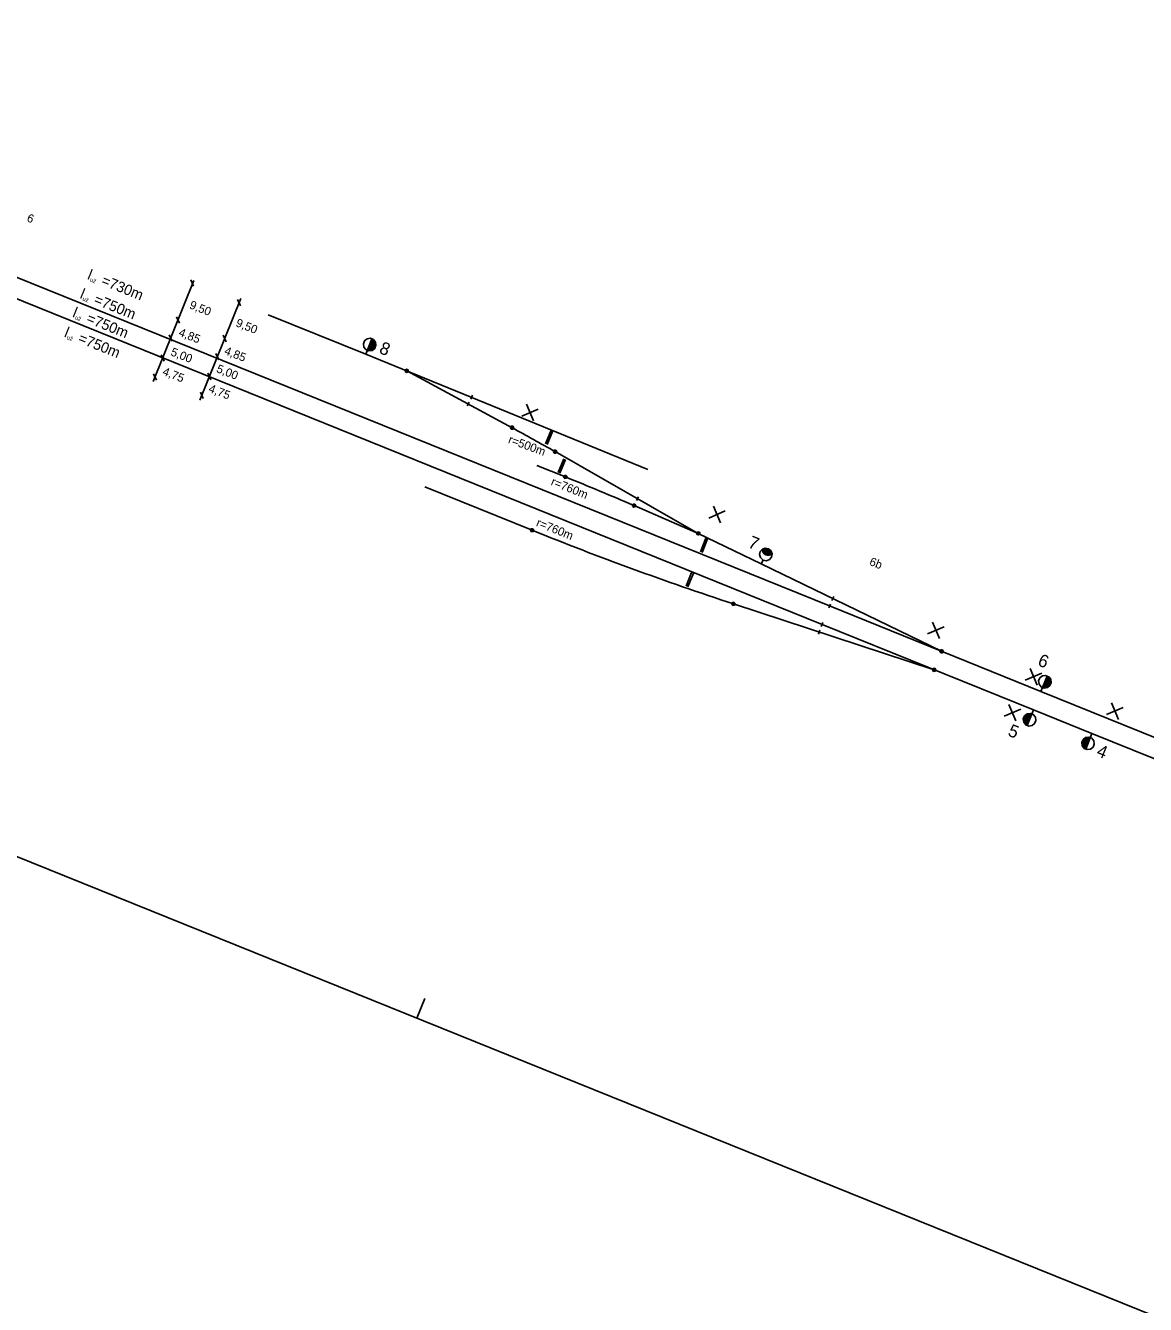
# Model space of a CAD drawing. Extents: x -467542 to -465211, y -1328177 to -1327037.
# Drawn here: x -466272 to -466005.7, y -1327930.8 to -1327626.7 of the extents above; entities that cross this region are included whole.
import ezdxf

# ---------------------------------------------------------------- set-up
doc = ezdxf.new("R2010")
doc.units = 0
for name, color, linetype in [('Level 1', 7, 'Continuous'), ('Level 10', 7, 'Continuous'), ('Level 11', 7, 'Continuous'), ('Level 61', 7, 'Continuous')]:
    doc.layers.add(name, color=color, linetype=linetype)

msp = doc.modelspace()

# ---------------------------------------------------------------- linework, layer by layer
at = {"layer": 'Level 1'}
for p, q in [((-466274.42, -1327686.43), (-466080.84, -1327764.72)), ((-466276.18, -1327690.84), (-466082.62, -1327769.13)), ((-466214.3, -1327695.52), (-466191.13, -1327704.89)), ((-466191.13, -1327704.89), (-466124.03, -1327732.27)), ((-466181.37, -1327708.84), (-466181.37, -1327708.84)), ((-466181.37, -1327708.84), (-466156.34, -1327722.35)), ((-466166.16, -1327715.53), (-466165.78, -1327714.6)), ((-466165.97, -1327715.07), (-466165.97, -1327715.07)), ((-466166.99, -1327717.17), (-466166.51, -1327716.29)), ((-466166.75, -1327716.73), (-466166.75, -1327716.73)), ((-466156.34, -1327722.35), (-466156.34, -1327722.35)), ((-466112.05, -1327747.46), (-466146.12, -1327728.03)), ((-466146.12, -1327728.03), (-466146.12, -1327728.03)), ((-466150.41, -1327731.3), (-466143.65, -1327734.04)), ((-466177.06, -1327736.41), (-466151.55, -1327746.72)), ((-466143.65, -1327734.04), (-466143.65, -1327734.04)), ((-466126.73, -1327739.66), (-466126.24, -1327738.79)), ((-466126.73, -1327739.66), (-466126.24, -1327738.79)), ((-466126.49, -1327739.22), (-466126.49, -1327739.22)), ((-466126.49, -1327739.22), (-466126.49, -1327739.22)), ((-466127.51, -1327741.33), (-466127.11, -1327740.41)), ((-466127.31, -1327740.87), (-466127.31, -1327740.87)), ((-466127.31, -1327740.87), (-466112.05, -1327747.46)), ((-466127.31, -1327740.87), (-466127.31, -1327740.87)), ((-466151.55, -1327746.72), (-466151.55, -1327746.72)), ((-466097.1, -1327754.7), (-466112.06, -1327747.46)), ((-466112.05, -1327747.46), (-466112.05, -1327747.46)), ((-466054.2, -1327775.5), (-466097.1, -1327754.7)), ((-466055.98, -1327779.9), (-466103.7, -1327764.23)), ((-466103.7, -1327764.23), (-466103.7, -1327764.23)), ((-466080.66, -1327764.26), (-466081.03, -1327765.19)), ((-466079.84, -1327762.51), (-466080.28, -1327763.41)), ((-466080.06, -1327762.96), (-466080.06, -1327762.96)), ((-466030.58, -1327785.05), (-466080.84, -1327764.72)), ((-466080.84, -1327764.72), (-466080.84, -1327764.72)), ((-466082.81, -1327769.59), (-466082.44, -1327768.66)), ((-466032.36, -1327789.45), (-466082.62, -1327769.13)), ((-466082.62, -1327769.13), (-466082.62, -1327769.13)), ((-466083.44, -1327771.41), (-466083.13, -1327770.46)), ((-466083.29, -1327770.94), (-466083.29, -1327770.94)), ((-466054.2, -1327775.5), (-466054.2, -1327775.5)), ((-466055.98, -1327779.9), (-466055.98, -1327779.9)), ((-466030.58, -1327785.05), (-465963.83, -1327812.05)), ((-466032.36, -1327789.45), (-466018.46, -1327795.08)), ((-466018.46, -1327795.08), (-465979.9, -1327810.67))]:
    msp.add_line(p, q, dxfattribs=at)
for points in [[(-466181, -1327708.99), (-466181.06, -1327708.59), (-466181.43, -1327708.44), (-466181.74, -1327708.69), (-466181.69, -1327709.08), (-466181.32, -1327709.23), (-466181, -1327708.99)], [(-466156.53, -1327722.7), (-466156.74, -1327722.36), (-466156.55, -1327722.01), (-466156.15, -1327722), (-466155.94, -1327722.34), (-466156.13, -1327722.69), (-466156.53, -1327722.7)], [(-466145.92, -1327727.68), (-466145.72, -1327728.02), (-466145.92, -1327728.37), (-466146.32, -1327728.37), (-466146.52, -1327728.03), (-466146.32, -1327727.68), (-466145.92, -1327727.68)], [(-466143.49, -1327733.67), (-466143.25, -1327733.98), (-466143.4, -1327734.35), (-466143.79, -1327734.41), (-466144.04, -1327734.09), (-466143.89, -1327733.72), (-466143.49, -1327733.67)], [(-466127.47, -1327741.24), (-466127.7, -1327740.92), (-466127.54, -1327740.55), (-466127.15, -1327740.5), (-466126.91, -1327740.82), (-466127.07, -1327741.19), (-466127.47, -1327741.24)], [(-466151.4, -1327746.35), (-466151.16, -1327746.67), (-466151.31, -1327747.03), (-466151.7, -1327747.09), (-466151.95, -1327746.78), (-466151.8, -1327746.41), (-466151.4, -1327746.35)], [(-466112.42, -1327747.3), (-466112.1, -1327747.06), (-466111.73, -1327747.22), (-466111.69, -1327747.61), (-466112.01, -1327747.85), (-466112.37, -1327747.7), (-466112.42, -1327747.3)], [(-466103.82, -1327764.61), (-466104.09, -1327764.32), (-466103.96, -1327763.94), (-466103.57, -1327763.85), (-466103.3, -1327764.15), (-466103.43, -1327764.53), (-466103.82, -1327764.61)], [(-466054.37, -1327775.86), (-466053.97, -1327775.83), (-466053.8, -1327775.47), (-466054.02, -1327775.14), (-466054.42, -1327775.17), (-466054.6, -1327775.53), (-466054.37, -1327775.86)], [(-466055.85, -1327779.52), (-466055.59, -1327779.82), (-466055.71, -1327780.2), (-466056.1, -1327780.28), (-466056.37, -1327779.98), (-466056.24, -1327779.6), (-466055.85, -1327779.52)]]:
    msp.add_lwpolyline(points, dxfattribs=at)
for centre, radius, start, end in [((-466393.87, -1328162.33), 500, 60.2972, 61.637), ((-466428.6, -1328438.6), 760, 66.64451, 67.97957), ((-465866.6, -1327042.17), 760, 247.97922, 251.82173)]:
    msp.add_arc(centre, radius, start, end, dxfattribs=at)
at = {"layer": 'Level 10'}
for p, q in [((-466232.01, -1327687.33), (-466241.65, -1327711.36)), ((-466232.07, -1327688.7), (-466232.74, -1327687.16)), ((-466220.86, -1327691.62), (-466230.56, -1327715.81)), ((-466220.94, -1327693.36), (-466221.61, -1327691.82)), ((-466235.44, -1327697.48), (-466236.11, -1327695.95)), ((-466237.17, -1327701.8), (-466237.84, -1327700.26)), ((-466224.34, -1327701.91), (-466225.01, -1327700.37)), ((-466239.07, -1327706.54), (-466239.75, -1327705.01)), ((-466226.08, -1327706.24), (-466226.75, -1327704.7)), ((-466240.88, -1327711.05), (-466241.55, -1327709.5)), ((-466227.96, -1327710.93), (-466228.63, -1327709.4)), ((-466229.75, -1327715.41), (-466230.43, -1327713.87)), ((-466147.07, -1327722.9), (-466148.38, -1327726.15)), ((-466146.65, -1327723.07), (-466147.96, -1327726.32)), ((-466144.05, -1327729.71), (-466145.36, -1327732.96)), ((-466143.62, -1327729.88), (-466144.94, -1327733.13)), ((-466110.26, -1327748.63), (-466111.57, -1327751.88)), ((-466109.84, -1327748.8), (-466111.15, -1327752.05)), ((-466113.66, -1327756.77), (-466114.97, -1327760.02)), ((-466113.23, -1327756.94), (-466114.55, -1327760.19))]:
    msp.add_line(p, q, dxfattribs=at)
at = {"layer": 'Level 11'}
for p, q in [((-466191.13, -1327704.89), (-466189.65, -1327701.23)), ((-466191.13, -1327704.89), (-466191.13, -1327704.89)), ((-466150.12, -1327717.9), (-466154.05, -1327719.57)), ((-466151.25, -1327720.7), (-466152.92, -1327716.77)), ((-466105.63, -1327742.14), (-466109.56, -1327743.81)), ((-466106.76, -1327744.94), (-466108.43, -1327741.01)), ((-466097.35, -1327751.8), (-466097.48, -1327752.52)), ((-466096.83, -1327751.22), (-466097.35, -1327751.8)), ((-466096.16, -1327750.95), (-466096.83, -1327751.22)), ((-466096.72, -1327751.87), (-466096.42, -1327751.25)), ((-466096.06, -1327751.21), (-466096.53, -1327752.15)), ((-466096.42, -1327751.25), (-466096.06, -1327751.21)), ((-466096.3, -1327752.37), (-466095.75, -1327751.25)), ((-466095.35, -1327751.11), (-466096.16, -1327750.95)), ((-466095.35, -1327751.11), (-466096.04, -1327752.53)), ((-466095.35, -1327751.11), (-466096.04, -1327752.53)), ((-466095.76, -1327752.63), (-466095.21, -1327751.51)), ((-466095.75, -1327751.25), (-466095.35, -1327751.11)), ((-466094.98, -1327751.73), (-466095.45, -1327752.68)), ((-466094.72, -1327751.67), (-466095.35, -1327751.11)), ((-466095.35, -1327751.11), (-466094.72, -1327751.65)), ((-466095.21, -1327751.51), (-466095.35, -1327751.11)), ((-466095.1, -1327752.66), (-466094.8, -1327752.04)), ((-466094.8, -1327752.04), (-466094.98, -1327751.73)), ((-466094.49, -1327752.36), (-466094.72, -1327751.67)), ((-466097.48, -1327752.52), (-466097.28, -1327753.24)), ((-466097.28, -1327753.24), (-466096.66, -1327753.8)), ((-466097.1, -1327754.7), (-466096.66, -1327753.8)), ((-466096.66, -1327753.8), (-466095.84, -1327753.96)), ((-466095.84, -1327753.96), (-466095.13, -1327753.69)), ((-466095.13, -1327753.69), (-466094.66, -1327753.11)), ((-466094.66, -1327753.11), (-466094.49, -1327752.36)), ((-466053.59, -1327769.67), (-466057.53, -1327771.34)), ((-466054.73, -1327772.48), (-466056.4, -1327768.54)), ((-466030.38, -1327780.73), (-466034.31, -1327782.4)), ((-466031.51, -1327783.53), (-466033.18, -1327779.59)), ((-466030.58, -1327785.05), (-466029.1, -1327781.39)), ((-466030.58, -1327785.05), (-466030.58, -1327785.05)), ((-466036.54, -1327792.06), (-466038.21, -1327788.13)), ((-466012.17, -1327791.68), (-466013.84, -1327787.74)), ((-466035.41, -1327789.26), (-466039.34, -1327790.93)), ((-466032.36, -1327789.45), (-466033.84, -1327793.11)), ((-466032.36, -1327789.45), (-466032.36, -1327789.45)), ((-466011.04, -1327788.87), (-466014.97, -1327790.54)), ((-466018.46, -1327795.08), (-466019.94, -1327798.74)), ((-466018.46, -1327795.08), (-466018.46, -1327795.08))]:
    msp.add_line(p, q, dxfattribs=at)
for points in [[(-466189.28, -1327701.38), (-466190.02, -1327701.08), (-466190.78, -1327701.19), (-466191.39, -1327701.66), (-466191.68, -1327702.4), (-466191.57, -1327703.16), (-466191.1, -1327703.77), (-466190.36, -1327704.07), (-466189.6, -1327703.96), (-466189, -1327703.49), (-466188.7, -1327702.75), (-466188.81, -1327701.99), (-466189.28, -1327701.38), (-466189.14, -1327701.71), (-466189.6, -1327701.52), (-466189.71, -1327701.8), (-466188.93, -1327702.11), (-466188.9, -1327702.45), (-466189.83, -1327702.07), (-466189.94, -1327702.35), (-466188.87, -1327702.78), (-466188.98, -1327703.06), (-466190.05, -1327702.63), (-466190.16, -1327702.91), (-466189.1, -1327703.34), (-466189.35, -1327703.56), (-466190.28, -1327703.19), (-466190.39, -1327703.47), (-466189.6, -1327703.78), (-466190.08, -1327703.91), (-466190.5, -1327703.74)], [(-466028.73, -1327781.54), (-466029.47, -1327781.24), (-466030.23, -1327781.35), (-466030.84, -1327781.82), (-466031.14, -1327782.56), (-466031.03, -1327783.32), (-466030.56, -1327783.93), (-466029.82, -1327784.23), (-466029.06, -1327784.11), (-466028.45, -1327783.65), (-466028.15, -1327782.91), (-466028.27, -1327782.15), (-466028.73, -1327781.54), (-466028.59, -1327781.86), (-466029.06, -1327781.68), (-466029.17, -1327781.96), (-466028.38, -1327782.27), (-466028.35, -1327782.61), (-466029.28, -1327782.23), (-466029.4, -1327782.51), (-466028.33, -1327782.94), (-466028.44, -1327783.22), (-466029.51, -1327782.79), (-466029.62, -1327783.07), (-466028.55, -1327783.5), (-466028.8, -1327783.72), (-466029.73, -1327783.35), (-466029.85, -1327783.62), (-466029.06, -1327783.94), (-466029.54, -1327784.07), (-466029.96, -1327783.9)], [(-466034.22, -1327792.97), (-466033.47, -1327793.27), (-466032.71, -1327793.15), (-466032.11, -1327792.69), (-466031.81, -1327791.94), (-466031.92, -1327791.19), (-466032.42, -1327790.56), (-466033.12, -1327790.28), (-466033.89, -1327790.39), (-466034.49, -1327790.86), (-466034.79, -1327791.6), (-466034.68, -1327792.36), (-466034.22, -1327792.97), (-466034.35, -1327792.64), (-466033.89, -1327792.83), (-466033.78, -1327792.55), (-466034.57, -1327792.23), (-466034.64, -1327791.88), (-466033.66, -1327792.27), (-466033.55, -1327791.99), (-466034.62, -1327791.56), (-466034.51, -1327791.28), (-466033.44, -1327791.72), (-466033.33, -1327791.44), (-466034.39, -1327791.01), (-466034.14, -1327790.78), (-466033.22, -1327791.16), (-466033.1, -1327790.88), (-466033.89, -1327790.56), (-466033.41, -1327790.43), (-466032.99, -1327790.6)], [(-466020.31, -1327798.59), (-466019.57, -1327798.89), (-466018.81, -1327798.78), (-466018.2, -1327798.31), (-466017.9, -1327797.57), (-466018.01, -1327796.81), (-466018.51, -1327796.18), (-466019.21, -1327795.91), (-466019.98, -1327796.02), (-466020.59, -1327796.48), (-466020.89, -1327797.22), (-466020.78, -1327797.98), (-466020.31, -1327798.59), (-466020.45, -1327798.27), (-466019.98, -1327798.45), (-466019.87, -1327798.17), (-466020.66, -1327797.86), (-466020.73, -1327797.5), (-466019.76, -1327797.9), (-466019.65, -1327797.62), (-466020.71, -1327797.19), (-466020.6, -1327796.91), (-466019.53, -1327797.34), (-466019.42, -1327797.06), (-466020.49, -1327796.63), (-466020.23, -1327796.41), (-466019.31, -1327796.78), (-466019.2, -1327796.51), (-466019.98, -1327796.19), (-466019.5, -1327796.06), (-466019.08, -1327796.23)]]:
    msp.add_lwpolyline(points, dxfattribs=at)
msp.add_arc((-466095.38, -1327751.18), 1.5, 182.2276, 305.7724, dxfattribs=at)
at = {"layer": 'Level 61'}
for p, q in [((-465400.15, -1328177.4), (-466763.11, -1327626.73)), ((-466178.98, -1327862.73), (-466177.11, -1327858.09))]:
    msp.add_line(p, q, dxfattribs=at)

# ---------------------------------------------------------------- texts
at = {"layer": 'Level 10'}
for s, height, rotation, p in [('l   =730m', 2.5, 338, (-466257.47, -1327686.93)), ('už', 1, 338, (-466256.81, -1327687.5)), ('l   =750m', 2.5, 338, (-466259.24, -1327691.47)), ('l   =750m', 2.5, 338, (-466261.01, -1327695.92)), ('už', 1, 338, (-466258.58, -1327692.04)), ('9,50', 2, 338.5471, (-466233.21, -1327693.9)), ('už', 1, 338, (-466260.35, -1327696.48)), ('9,50', 2, 338.5471, (-466222.19, -1327698.17)), ('l   =750m', 2.5, 338, (-466262.98, -1327700.65)), ('4,85', 2, 338.5471, (-466235.78, -1327700.43)), ('už', 1, 338, (-466262.32, -1327701.22)), ('5,00', 2, 338.5471, (-466237.67, -1327705.08)), ('4,85', 2, 338.5471, (-466224.92, -1327704.8)), ('4,75', 2, 338.5471, (-466239.61, -1327709.72)), ('5,00', 2, 338.5471, (-466226.79, -1327709.08)), ('4,75', 2, 338.5471, (-466228.66, -1327713.77)), ('r=500m', 2, 340, (-466157.4, -1327725.93)), ('r=760m', 2, 338, (-466147.25, -1327735.9)), ('r=760m', 2, 338, (-466150.75, -1327745.65))]:
    msp.add_text(s, height=height, rotation=rotation, dxfattribs=at).set_placement(p)
at = {"layer": 'Level 11'}
for s, height, p in [('6', 2, (-466271.88, -1327673.21)), ('8', 3, (-466188.14, -1327704.52)), ('7', 3, (-466100.43, -1327750.7)), ('6b', 2, (-466071.55, -1327754.91)), ('6', 3, (-466031.56, -1327778.77)), ('5', 3, (-466038.66, -1327795.48)), ('4', 3, (-466017.59, -1327800.3))]:
    msp.add_text(s, height=height, rotation=338, dxfattribs=at).set_placement(p)

doc.saveas('drawing.dxf')
